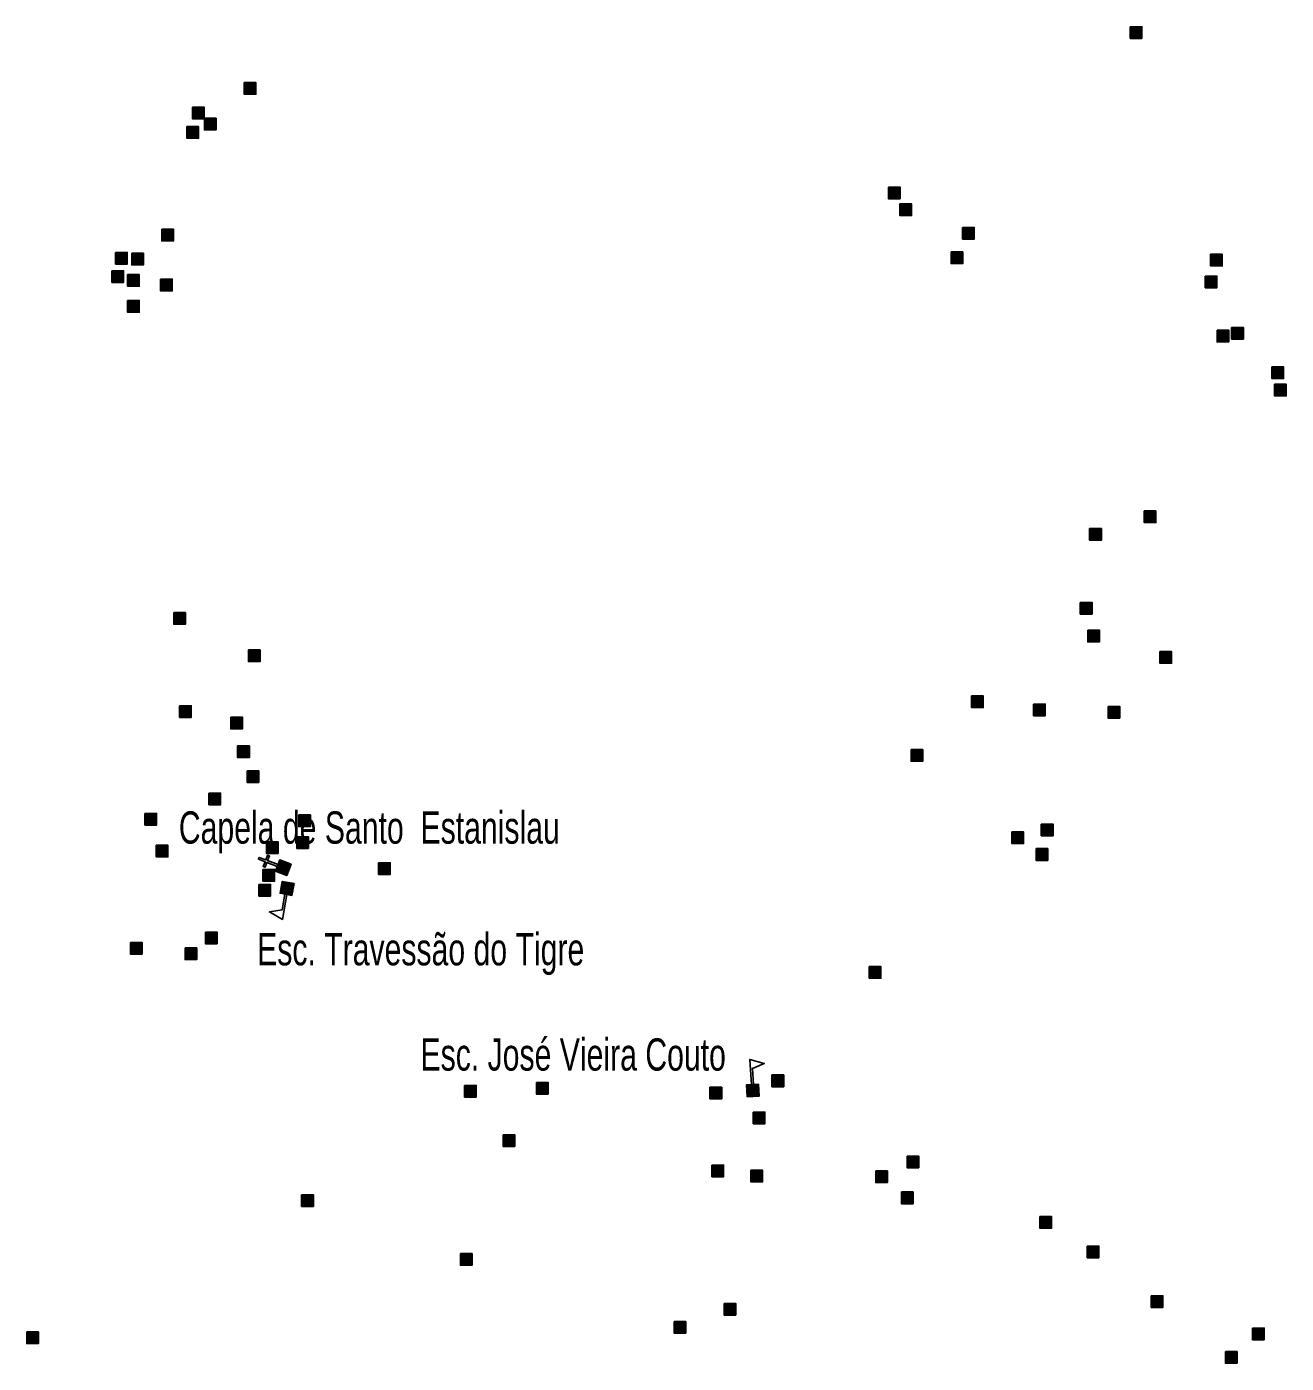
# Model space of a CAD drawing. Extents: x 649.2 to 674.4, y 7040 to 7068.1.
# Drawn here: x 661.863 to 664.987, y 7040.178 to 7043.493 of the extents above; entities that cross this region are included whole.
import ezdxf
from ezdxf.enums import TextEntityAlignment as Align

# ---------------------------------------------------------------- set-up
doc = ezdxf.new("R2010")
doc.units = 0
doc.header["$LTSCALE"] = 0.032
for name, color, linetype, lineweight in [('2', 7, 'Continuous', 25), ('4', 7, 'Continuous', 25), ('6', 7, 'Continuous', 25)]:
    doc.layers.add(name, color=color, linetype=linetype, lineweight=lineweight)
doc.layers.add('61', color=7, linetype='Continuous')

msp = doc.modelspace()

# ---------------------------------------------------------------- hatches: boundary and pattern name
at = {"layer": '2'}
for points in [[(664.6001, 7043.4933), (664.6291, 7043.4933), (664.6291, 7043.4643), (664.6001, 7043.4643)], [(662.4022, 7043.3549), (662.4312, 7043.3549), (662.4312, 7043.3259), (662.4022, 7043.3259)], [(662.2741, 7043.2936), (662.3031, 7043.2936), (662.3031, 7043.2646), (662.2741, 7043.2646)], [(662.3032, 7043.2664), (662.3322, 7043.2664), (662.3322, 7043.2374), (662.3032, 7043.2374)], [(662.2601, 7043.2455), (662.2891, 7043.2455), (662.2891, 7043.2165), (662.2601, 7043.2165)], [(663.9999, 7043.0955), (664.0289, 7043.0955), (664.0289, 7043.0665), (663.9999, 7043.0665)], [(664.0286, 7043.0537), (664.0576, 7043.0537), (664.0576, 7043.0247), (664.0286, 7043.0247)], [(662.1977, 7042.9908), (662.2267, 7042.9908), (662.2267, 7042.9618), (662.1977, 7042.9618)], [(664.1842, 7042.9955), (664.2132, 7042.9955), (664.2132, 7042.9665), (664.1842, 7042.9665)], [(662.083, 7042.9334), (662.112, 7042.9334), (662.112, 7042.9044), (662.083, 7042.9044)], [(662.1231, 7042.9315), (662.1521, 7042.9315), (662.1521, 7042.9025), (662.1231, 7042.9025)], [(664.1555, 7042.9347), (664.1845, 7042.9347), (664.1845, 7042.9057), (664.1555, 7042.9057)], [(664.7993, 7042.9288), (664.8283, 7042.9288), (664.8283, 7042.8998), (664.7993, 7042.8998)], [(662.074, 7042.8881), (662.103, 7042.8881), (662.103, 7042.8591), (662.074, 7042.8591)], [(662.1129, 7042.8786), (662.1419, 7042.8786), (662.1419, 7042.8496), (662.1129, 7042.8496)], [(662.1945, 7042.8671), (662.2235, 7042.8671), (662.2235, 7042.8381), (662.1945, 7042.8381)], [(664.786, 7042.8746), (664.815, 7042.8746), (664.815, 7042.8456), (664.786, 7042.8456)], [(662.1129, 7042.8142), (662.1419, 7042.8142), (662.1419, 7042.7852), (662.1129, 7042.7852)], [(664.8154, 7042.7406), (664.8444, 7042.7406), (664.8444, 7042.7116), (664.8154, 7042.7116)], [(664.8515, 7042.7473), (664.8805, 7042.7473), (664.8805, 7042.7183), (664.8515, 7042.7183)], [(664.9513, 7042.6494), (664.9803, 7042.6494), (664.9803, 7042.6204), (664.9513, 7042.6204)], [(664.958, 7042.6066), (664.987, 7042.6066), (664.987, 7042.5776), (664.958, 7042.5776)], [(664.6348, 7042.2923), (664.6638, 7042.2923), (664.6638, 7042.2633), (664.6348, 7042.2633)], [(664.4993, 7042.2483), (664.5283, 7042.2483), (664.5283, 7042.2193), (664.4993, 7042.2193)], [(664.4761, 7042.0653), (664.5051, 7042.0653), (664.5051, 7042.0363), (664.4761, 7042.0363)], [(662.2274, 7042.04), (662.2564, 7042.04), (662.2564, 7042.011), (662.2274, 7042.011)], [(664.4946, 7041.9964), (664.5236, 7041.9964), (664.5236, 7041.9674), (664.4946, 7041.9674)], [(662.4125, 7041.9475), (662.4415, 7041.9475), (662.4415, 7041.9185), (662.4125, 7041.9185)], [(664.6735, 7041.9434), (664.7025, 7041.9434), (664.7025, 7041.9144), (664.6735, 7041.9144)], [(664.2063, 7041.8334), (664.2353, 7041.8334), (664.2353, 7041.8044), (664.2063, 7041.8044)], [(662.2418, 7041.8089), (662.2708, 7041.8089), (662.2708, 7041.7799), (662.2418, 7041.7799)], [(664.3601, 7041.8132), (664.3891, 7041.8132), (664.3891, 7041.7842), (664.3601, 7041.7842)], [(664.545, 7041.8073), (664.574, 7041.8073), (664.574, 7041.7783), (664.545, 7041.7783)], [(662.3685, 7041.7806), (662.3975, 7041.7806), (662.3975, 7041.7516), (662.3685, 7041.7516)], [(662.3858, 7041.7092), (662.4148, 7041.7092), (662.4148, 7041.6802), (662.3858, 7041.6802)], [(664.0564, 7041.7002), (664.0854, 7041.7002), (664.0854, 7041.6712), (664.0564, 7041.6712)], [(662.4092, 7041.6476), (662.4382, 7041.6476), (662.4382, 7041.6186), (662.4092, 7041.6186)], [(662.3144, 7041.5922), (662.3434, 7041.5922), (662.3434, 7041.5632), (662.3144, 7041.5632)], [(662.1556, 7041.5418), (662.1846, 7041.5418), (662.1846, 7041.5128), (662.1556, 7041.5128)], [(662.5372, 7041.5381), (662.5662, 7041.5381), (662.5662, 7041.5091), (662.5372, 7041.5091)], [(664.3063, 7041.496), (664.3353, 7041.496), (664.3353, 7041.467), (664.3063, 7041.467)], [(664.3794, 7041.5153), (664.4084, 7041.5153), (664.4084, 7041.4863), (664.3794, 7041.4863)], [(662.1839, 7041.463), (662.2129, 7041.463), (662.2129, 7041.434), (662.1839, 7041.434)], [(662.4572, 7041.4716), (662.4862, 7041.4716), (662.4862, 7041.4426), (662.4572, 7041.4426)], [(662.5323, 7041.4839), (662.5613, 7041.4839), (662.5613, 7041.4549), (662.5323, 7041.4549)], [(664.3662, 7041.4544), (664.3952, 7041.4544), (664.3952, 7041.4254), (664.3662, 7041.4254)], [(662.4486, 7041.4027), (662.4776, 7041.4027), (662.4776, 7041.3737), (662.4486, 7041.3737)], [(662.7353, 7041.4196), (662.7643, 7041.4196), (662.7643, 7041.3906), (662.7353, 7041.3906)], [(662.4387, 7041.3657), (662.4677, 7041.3657), (662.4677, 7041.3367), (662.4387, 7041.3367)], [(662.3058, 7041.2475), (662.3348, 7041.2475), (662.3348, 7041.2185), (662.3058, 7041.2185)], [(662.1199, 7041.2217), (662.1489, 7041.2217), (662.1489, 7041.1927), (662.1199, 7041.1927)], [(662.2553, 7041.2082), (662.2843, 7041.2082), (662.2843, 7041.1792), (662.2553, 7041.1792)], [(663.9526, 7041.1618), (663.9816, 7041.1618), (663.9816, 7041.1328), (663.9526, 7041.1328)], [(662.9487, 7040.8671), (662.9777, 7040.8671), (662.9777, 7040.8381), (662.9487, 7040.8381)], [(663.1268, 7040.8745), (663.1558, 7040.8745), (663.1558, 7040.8455), (663.1268, 7040.8455)], [(663.5575, 7040.8626), (663.5865, 7040.8626), (663.5865, 7040.8336), (663.5575, 7040.8336)], [(663.7113, 7040.8929), (663.7403, 7040.8929), (663.7403, 7040.8639), (663.7113, 7040.8639)], [(663.6647, 7040.8009), (663.6937, 7040.8009), (663.6937, 7040.7719), (663.6647, 7040.7719)], [(663.0442, 7040.7447), (663.0732, 7040.7447), (663.0732, 7040.7157), (663.0442, 7040.7157)], [(663.5622, 7040.6693), (663.5912, 7040.6693), (663.5912, 7040.6403), (663.5622, 7040.6403)], [(664.0463, 7040.6919), (664.0753, 7040.6919), (664.0753, 7040.6629), (664.0463, 7040.6629)], [(663.6589, 7040.6565), (663.6879, 7040.6565), (663.6879, 7040.6275), (663.6589, 7040.6275)], [(663.9686, 7040.6549), (663.9976, 7040.6549), (663.9976, 7040.6259), (663.9686, 7040.6259)], [(664.0322, 7040.6027), (664.0612, 7040.6027), (664.0612, 7040.5737), (664.0322, 7040.5737)], [(662.5446, 7040.5959), (662.5736, 7040.5959), (662.5736, 7040.5669), (662.5446, 7040.5669)], [(664.3758, 7040.5418), (664.4048, 7040.5418), (664.4048, 7040.5128), (664.3758, 7040.5128)], [(664.4932, 7040.4685), (664.5222, 7040.4685), (664.5222, 7040.4395), (664.4932, 7040.4395)], [(662.9385, 7040.4498), (662.9675, 7040.4498), (662.9675, 7040.4208), (662.9385, 7040.4208)], [(664.652, 7040.3452), (664.681, 7040.3452), (664.681, 7040.3162), (664.652, 7040.3162)], [(663.5923, 7040.3262), (663.6213, 7040.3262), (663.6213, 7040.2972), (663.5923, 7040.2972)], [(663.4683, 7040.2817), (663.4973, 7040.2817), (663.4973, 7040.2527), (663.4683, 7040.2527)], [(661.8626, 7040.2555), (661.8916, 7040.2555), (661.8916, 7040.2265), (661.8626, 7040.2265)], [(664.9034, 7040.2652), (664.9324, 7040.2652), (664.9324, 7040.2362), (664.9034, 7040.2362)], [(664.8361, 7040.2068), (664.8651, 7040.2068), (664.8651, 7040.1778), (664.8361, 7040.1778)]]:
    msp.add_hatch(color=256, dxfattribs=at).paths.add_polyline_path(points)
at = {"layer": '4'}
for points in [[(662.5258, 7041.3678), (662.5204, 7041.3383), (662.4909, 7041.3437), (662.4963, 7041.3732)], [(663.6498, 7040.8386), (663.6478, 7040.8685), (663.6777, 7040.8705), (663.6797, 7040.8406)]]:
    msp.add_hatch(color=256, dxfattribs=at).paths.add_polyline_path(points)
at = {"layer": '6'}
for points in [[(662.4859, 7041.4149), (662.4841, 7041.4101), (662.4584, 7041.42), (662.454, 7041.4082), (662.4494, 7041.4101), (662.4538, 7041.4217), (662.4374, 7041.428), (662.4391, 7041.4327), (662.4556, 7041.4263), (662.46, 7041.4381), (662.4646, 7041.4362), (662.4602, 7041.4246)], [(662.4797, 7041.3985), (662.5077, 7041.3877), (662.5184, 7041.4158), (662.4904, 7041.4265)]]:
    msp.add_hatch(color=256, dxfattribs=at).paths.add_polyline_path(points)

# ---------------------------------------------------------------- linework, layer by layer
at = {"layer": '2'}
for points in [[(664.6001, 7043.4933), (664.6291, 7043.4933), (664.6291, 7043.4643), (664.6001, 7043.4643)], [(662.4022, 7043.3549), (662.4312, 7043.3549), (662.4312, 7043.3259), (662.4022, 7043.3259)], [(662.2741, 7043.2936), (662.3031, 7043.2936), (662.3031, 7043.2646), (662.2741, 7043.2646)], [(662.3032, 7043.2664), (662.3322, 7043.2664), (662.3322, 7043.2374), (662.3032, 7043.2374)], [(662.2601, 7043.2455), (662.2891, 7043.2455), (662.2891, 7043.2165), (662.2601, 7043.2165)], [(663.9999, 7043.0955), (664.0289, 7043.0955), (664.0289, 7043.0665), (663.9999, 7043.0665)], [(664.0286, 7043.0537), (664.0576, 7043.0537), (664.0576, 7043.0247), (664.0286, 7043.0247)], [(662.1977, 7042.9908), (662.2267, 7042.9908), (662.2267, 7042.9618), (662.1977, 7042.9618)], [(664.1842, 7042.9955), (664.2132, 7042.9955), (664.2132, 7042.9665), (664.1842, 7042.9665)], [(662.083, 7042.9334), (662.112, 7042.9334), (662.112, 7042.9044), (662.083, 7042.9044)], [(662.1231, 7042.9315), (662.1521, 7042.9315), (662.1521, 7042.9025), (662.1231, 7042.9025)], [(664.1555, 7042.9347), (664.1845, 7042.9347), (664.1845, 7042.9057), (664.1555, 7042.9057)], [(664.7993, 7042.9288), (664.8283, 7042.9288), (664.8283, 7042.8998), (664.7993, 7042.8998)], [(662.074, 7042.8881), (662.103, 7042.8881), (662.103, 7042.8591), (662.074, 7042.8591)], [(662.1129, 7042.8786), (662.1419, 7042.8786), (662.1419, 7042.8496), (662.1129, 7042.8496)], [(662.1945, 7042.8671), (662.2235, 7042.8671), (662.2235, 7042.8381), (662.1945, 7042.8381)], [(664.786, 7042.8746), (664.815, 7042.8746), (664.815, 7042.8456), (664.786, 7042.8456)], [(662.1129, 7042.8142), (662.1419, 7042.8142), (662.1419, 7042.7852), (662.1129, 7042.7852)], [(664.8154, 7042.7406), (664.8444, 7042.7406), (664.8444, 7042.7116), (664.8154, 7042.7116)], [(664.8515, 7042.7473), (664.8805, 7042.7473), (664.8805, 7042.7183), (664.8515, 7042.7183)], [(664.9513, 7042.6494), (664.9803, 7042.6494), (664.9803, 7042.6204), (664.9513, 7042.6204)], [(664.958, 7042.6066), (664.987, 7042.6066), (664.987, 7042.5776), (664.958, 7042.5776)], [(664.6348, 7042.2923), (664.6638, 7042.2923), (664.6638, 7042.2633), (664.6348, 7042.2633)], [(664.4993, 7042.2483), (664.5283, 7042.2483), (664.5283, 7042.2193), (664.4993, 7042.2193)], [(664.4761, 7042.0653), (664.5051, 7042.0653), (664.5051, 7042.0363), (664.4761, 7042.0363)], [(662.2274, 7042.04), (662.2564, 7042.04), (662.2564, 7042.011), (662.2274, 7042.011)], [(664.4946, 7041.9964), (664.5236, 7041.9964), (664.5236, 7041.9674), (664.4946, 7041.9674)], [(662.4125, 7041.9475), (662.4415, 7041.9475), (662.4415, 7041.9185), (662.4125, 7041.9185)], [(664.6735, 7041.9434), (664.7025, 7041.9434), (664.7025, 7041.9144), (664.6735, 7041.9144)], [(664.2063, 7041.8334), (664.2353, 7041.8334), (664.2353, 7041.8044), (664.2063, 7041.8044)], [(662.2418, 7041.8089), (662.2708, 7041.8089), (662.2708, 7041.7799), (662.2418, 7041.7799)], [(664.3601, 7041.8132), (664.3891, 7041.8132), (664.3891, 7041.7842), (664.3601, 7041.7842)], [(664.545, 7041.8073), (664.574, 7041.8073), (664.574, 7041.7783), (664.545, 7041.7783)], [(662.3685, 7041.7806), (662.3975, 7041.7806), (662.3975, 7041.7516), (662.3685, 7041.7516)], [(662.3858, 7041.7092), (662.4148, 7041.7092), (662.4148, 7041.6802), (662.3858, 7041.6802)], [(664.0564, 7041.7002), (664.0854, 7041.7002), (664.0854, 7041.6712), (664.0564, 7041.6712)], [(662.4092, 7041.6476), (662.4382, 7041.6476), (662.4382, 7041.6186), (662.4092, 7041.6186)], [(662.3144, 7041.5922), (662.3434, 7041.5922), (662.3434, 7041.5632), (662.3144, 7041.5632)], [(662.1556, 7041.5418), (662.1846, 7041.5418), (662.1846, 7041.5128), (662.1556, 7041.5128)], [(662.5372, 7041.5381), (662.5662, 7041.5381), (662.5662, 7041.5091), (662.5372, 7041.5091)], [(664.3063, 7041.496), (664.3353, 7041.496), (664.3353, 7041.467), (664.3063, 7041.467)], [(664.3794, 7041.5153), (664.4084, 7041.5153), (664.4084, 7041.4863), (664.3794, 7041.4863)], [(662.1839, 7041.463), (662.2129, 7041.463), (662.2129, 7041.434), (662.1839, 7041.434)], [(662.4572, 7041.4716), (662.4862, 7041.4716), (662.4862, 7041.4426), (662.4572, 7041.4426)], [(662.5323, 7041.4839), (662.5613, 7041.4839), (662.5613, 7041.4549), (662.5323, 7041.4549)], [(664.3662, 7041.4544), (664.3952, 7041.4544), (664.3952, 7041.4254), (664.3662, 7041.4254)], [(662.4486, 7041.4027), (662.4776, 7041.4027), (662.4776, 7041.3737), (662.4486, 7041.3737)], [(662.7353, 7041.4196), (662.7643, 7041.4196), (662.7643, 7041.3906), (662.7353, 7041.3906)], [(662.4387, 7041.3657), (662.4677, 7041.3657), (662.4677, 7041.3367), (662.4387, 7041.3367)], [(662.3058, 7041.2475), (662.3348, 7041.2475), (662.3348, 7041.2185), (662.3058, 7041.2185)], [(662.1199, 7041.2217), (662.1489, 7041.2217), (662.1489, 7041.1927), (662.1199, 7041.1927)], [(662.2553, 7041.2082), (662.2843, 7041.2082), (662.2843, 7041.1792), (662.2553, 7041.1792)], [(663.9526, 7041.1618), (663.9816, 7041.1618), (663.9816, 7041.1328), (663.9526, 7041.1328)], [(662.9487, 7040.8671), (662.9777, 7040.8671), (662.9777, 7040.8381), (662.9487, 7040.8381)], [(663.1268, 7040.8745), (663.1558, 7040.8745), (663.1558, 7040.8455), (663.1268, 7040.8455)], [(663.5575, 7040.8626), (663.5865, 7040.8626), (663.5865, 7040.8336), (663.5575, 7040.8336)], [(663.7113, 7040.8929), (663.7403, 7040.8929), (663.7403, 7040.8639), (663.7113, 7040.8639)], [(663.6647, 7040.8009), (663.6937, 7040.8009), (663.6937, 7040.7719), (663.6647, 7040.7719)], [(663.0442, 7040.7447), (663.0732, 7040.7447), (663.0732, 7040.7157), (663.0442, 7040.7157)], [(663.5622, 7040.6693), (663.5912, 7040.6693), (663.5912, 7040.6403), (663.5622, 7040.6403)], [(664.0463, 7040.6919), (664.0753, 7040.6919), (664.0753, 7040.6629), (664.0463, 7040.6629)], [(663.6589, 7040.6565), (663.6879, 7040.6565), (663.6879, 7040.6275), (663.6589, 7040.6275)], [(663.9686, 7040.6549), (663.9976, 7040.6549), (663.9976, 7040.6259), (663.9686, 7040.6259)], [(664.0322, 7040.6027), (664.0612, 7040.6027), (664.0612, 7040.5737), (664.0322, 7040.5737)], [(662.5446, 7040.5959), (662.5736, 7040.5959), (662.5736, 7040.5669), (662.5446, 7040.5669)], [(664.3758, 7040.5418), (664.4048, 7040.5418), (664.4048, 7040.5128), (664.3758, 7040.5128)], [(664.4932, 7040.4685), (664.5222, 7040.4685), (664.5222, 7040.4395), (664.4932, 7040.4395)], [(662.9385, 7040.4498), (662.9675, 7040.4498), (662.9675, 7040.4208), (662.9385, 7040.4208)], [(664.652, 7040.3452), (664.681, 7040.3452), (664.681, 7040.3162), (664.652, 7040.3162)], [(663.5923, 7040.3262), (663.6213, 7040.3262), (663.6213, 7040.2972), (663.5923, 7040.2972)], [(663.4683, 7040.2817), (663.4973, 7040.2817), (663.4973, 7040.2527), (663.4683, 7040.2527)], [(661.8626, 7040.2555), (661.8916, 7040.2555), (661.8916, 7040.2265), (661.8626, 7040.2265)], [(664.9034, 7040.2652), (664.9324, 7040.2652), (664.9324, 7040.2362), (664.9034, 7040.2362)], [(664.8361, 7040.2068), (664.8651, 7040.2068), (664.8651, 7040.1778), (664.8361, 7040.1778)]]:
    msp.add_lwpolyline(points, close=True, dxfattribs=at)
at = {"layer": '4'}
for p, q in [((662.5081, 7041.3405), (662.5032, 7041.3414)), ((663.6602, 7040.8693), (663.6652, 7040.8697))]:
    msp.add_line(p, q, dxfattribs=at)
for points in [[(662.5258, 7041.3678), (662.5204, 7041.3383), (662.4909, 7041.3437), (662.4963, 7041.3732)], [(662.5081, 7041.3405), (662.4969, 7041.279), (662.4647, 7041.2976), (662.4961, 7041.3026), (662.5032, 7041.3414)], [(663.6602, 7040.8693), (663.6561, 7040.9317), (663.6919, 7040.9215), (663.6626, 7040.9091), (663.6652, 7040.8697)], [(663.6498, 7040.8386), (663.6478, 7040.8685), (663.6777, 7040.8705), (663.6797, 7040.8406)]]:
    msp.add_lwpolyline(points, close=True, dxfattribs=at)
at = {"layer": '6'}
for points in [[(662.4859, 7041.4149), (662.4841, 7041.4101), (662.4584, 7041.42), (662.454, 7041.4082), (662.4494, 7041.4101), (662.4538, 7041.4217), (662.4374, 7041.428), (662.4391, 7041.4327), (662.4556, 7041.4263), (662.46, 7041.4381), (662.4646, 7041.4362), (662.4602, 7041.4246)], [(662.4797, 7041.3985), (662.5077, 7041.3877), (662.5184, 7041.4158), (662.4904, 7041.4265)]]:
    msp.add_lwpolyline(points, close=True, dxfattribs=at)

# ---------------------------------------------------------------- texts
at = {"layer": '61', "width": 0.7}
for s, p in [('Capela de Santo  Estanislau', (662.2399, 7041.4668)), ('Esc. Travessão do Tigre', (662.4341, 7041.1649))]:
    msp.add_text(s, height=0.08, dxfattribs=at).set_placement(p)
msp.add_text('Esc. José Vieira Couto', height=0.08, dxfattribs=at).set_placement((663.5969, 7040.9038), align=Align.RIGHT)

doc.saveas('drawing.dxf')
